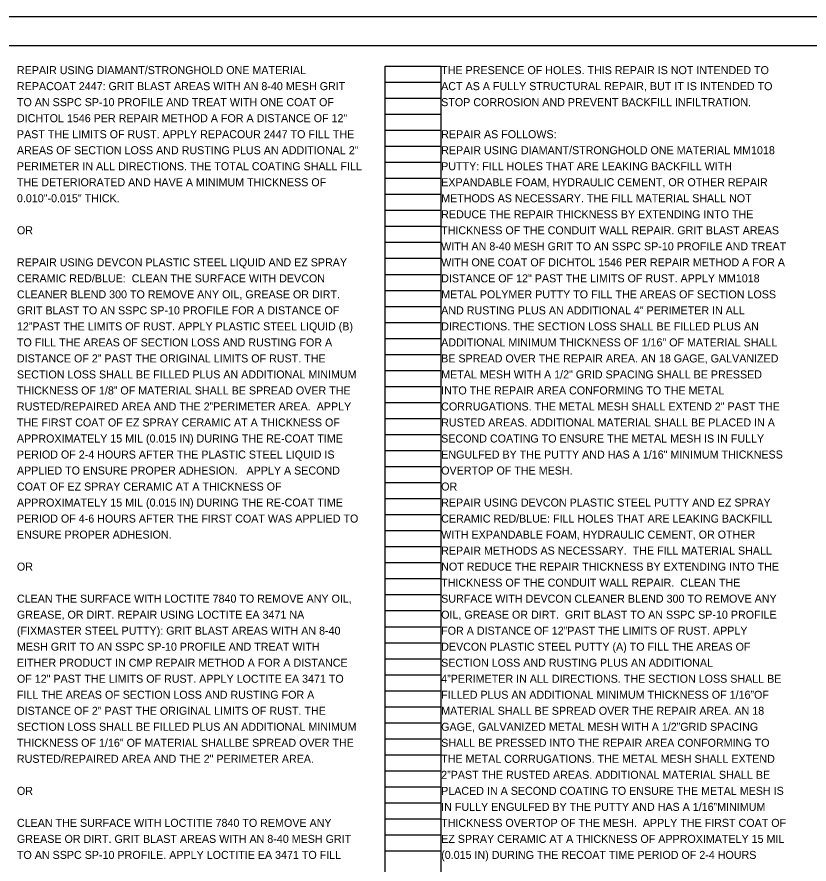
# Model space of a CAD drawing. Extents: x 0 to 42.3, y -7.4 to 22.
# Drawn here: x 9.82 to 23.67, y 7.19 to 22 of the extents above; entities that cross this region are included whole.
import ezdxf

# ---------------------------------------------------------------- set-up
doc = ezdxf.new("R2010")
doc.units = 0
for name, color, linetype in [('SH_Border', 7, 'Continuous'), ('SH_Cut_Line', 7, 'Continuous'), ('SH_Data', 7, 'Continuous'), ('SH_Text', 7, 'Continuous')]:
    doc.layers.add(name, color=color, linetype=linetype)

msp = doc.modelspace()

# ---------------------------------------------------------------- linework, layer by layer
at = {"layer": 'SH_Border'}
msp.add_lwpolyline([(1.5, 21.5), (33.5, 21.5), (33.5, 0.5), (1.5, 0.5)], close=True, dxfattribs=at)
at = {"layer": 'SH_Cut_Line'}
msp.add_lwpolyline([(0, 0), (34, 0), (34, 22), (0, 22)], close=True, dxfattribs=at)
at = {"layer": 'SH_Data'}
for p, q in [((16.26, 0.98), (16.26, 21.14)), ((16.26, 21.14), (17.24, 21.14)), ((17.24, 0.98), (17.24, 21.14)), ((16.26, 20.86), (17.24, 20.86)), ((16.26, 20.58), (17.24, 20.58)), ((16.26, 20.3), (17.24, 20.3)), ((16.26, 20.02), (17.24, 20.02)), ((16.26, 19.74), (17.24, 19.74)), ((16.26, 19.46), (17.24, 19.46)), ((16.26, 19.18), (17.24, 19.18)), ((16.26, 18.9), (17.24, 18.9)), ((16.26, 18.62), (17.24, 18.62)), ((16.26, 18.34), (17.24, 18.34)), ((16.26, 18.06), (17.24, 18.06)), ((16.26, 17.78), (17.24, 17.78)), ((16.26, 17.5), (17.24, 17.5)), ((16.26, 17.22), (17.24, 17.22)), ((16.26, 16.94), (17.24, 16.94)), ((16.26, 16.66), (17.24, 16.66)), ((16.26, 16.38), (17.24, 16.38)), ((16.26, 16.1), (17.24, 16.1)), ((16.26, 15.82), (17.24, 15.82)), ((16.26, 15.54), (17.24, 15.54)), ((16.26, 15.26), (17.24, 15.26)), ((16.26, 14.98), (17.24, 14.98)), ((16.26, 14.7), (17.24, 14.7)), ((16.26, 14.42), (17.24, 14.42)), ((16.26, 14.14), (17.24, 14.14)), ((16.26, 13.86), (17.24, 13.86)), ((16.26, 13.58), (17.24, 13.58)), ((16.26, 13.3), (17.24, 13.3)), ((16.26, 13.02), (17.24, 13.02)), ((16.26, 12.74), (17.24, 12.74)), ((16.26, 12.46), (17.24, 12.46)), ((16.26, 12.18), (17.24, 12.18)), ((16.26, 11.9), (17.24, 11.9)), ((16.26, 11.62), (17.24, 11.62)), ((16.26, 11.34), (17.24, 11.34)), ((16.26, 11.06), (17.24, 11.06)), ((16.26, 10.78), (17.24, 10.78)), ((16.26, 10.5), (17.24, 10.5)), ((16.26, 10.22), (17.24, 10.22)), ((16.26, 9.94), (17.24, 9.94)), ((16.26, 9.66), (17.24, 9.66)), ((16.26, 9.38), (17.24, 9.38)), ((16.26, 9.1), (17.24, 9.1)), ((16.26, 8.82), (17.24, 8.82)), ((16.26, 8.54), (17.24, 8.54)), ((16.26, 8.26), (17.24, 8.26)), ((16.26, 7.98), (17.24, 7.98)), ((16.26, 7.7), (17.24, 7.7)), ((16.26, 7.42), (17.24, 7.42))]:
    msp.add_line(p, q, dxfattribs=at)

# ---------------------------------------------------------------- texts
at = {"layer": 'SH_Text'}
for s, p in [('REPAIR USING DIAMANT/STRONGHOLD ONE MATERIAL ', (9.82, 21)), ('THE PRESENCE OF HOLES. THIS REPAIR IS NOT INTENDED TO ', (17.24, 21)), ('REPACOAT 2447: GRIT BLAST AREAS WITH AN 8-40 MESH GRIT ', (9.82, 20.72)), ('ACT AS A FULLY STRUCTURAL REPAIR, BUT IT IS INTENDED TO ', (17.24, 20.72)), ('TO AN SSPC SP-10 PROFILE AND TREAT WITH ONE COAT OF ', (9.82, 20.44)), ('STOP CORROSION AND PREVENT BACKFILL INFILTRATION.', (17.24, 20.44)), ('DICHTOL 1546 PER REPAIR METHOD A FOR A DISTANCE OF 12" ', (9.82, 20.16)), ('PAST THE LIMITS OF RUST. APPLY REPACOUR 2447 TO FILL THE ', (9.82, 19.88)), ('REPAIR AS FOLLOWS:', (17.24, 19.88)), ('AREAS OF SECTION LOSS AND RUSTING PLUS AN ADDITIONAL 2" ', (9.82, 19.6)), ('REPAIR USING DIAMANT/STRONGHOLD ONE MATERIAL MM1018 ', (17.24, 19.6)), ('PERIMETER IN ALL DIRECTIONS. THE TOTAL COATING SHALL FILL ', (9.82, 19.32)), ('PUTTY: FILL HOLES THAT ARE LEAKING BACKFILL WITH ', (17.24, 19.32)), ('THE DETERIORATED AND HAVE A MINIMUM THICKNESS OF ', (9.82, 19.04)), ('EXPANDABLE FOAM, HYDRAULIC CEMENT, OR OTHER REPAIR ', (17.24, 19.04)), ('0.010"-0.015" THICK.', (9.82, 18.76)), ('METHODS AS NECESSARY. THE FILL MATERIAL SHALL NOT ', (17.24, 18.76)), ('REDUCE THE REPAIR THICKNESS BY EXTENDING INTO THE ', (17.24, 18.48)), ('OR', (9.82, 18.2)), ('THICKNESS OF THE CONDUIT WALL REPAIR. GRIT BLAST AREAS ', (17.24, 18.2)), ('WITH AN 8-40 MESH GRIT TO AN SSPC SP-10 PROFILE AND TREAT ', (17.24, 17.92)), ('REPAIR USING DEVCON PLASTIC STEEL LIQUID AND EZ SPRAY ', (9.82, 17.64)), ('WITH ONE COAT OF DICHTOL 1546 PER REPAIR METHOD A FOR A ', (17.24, 17.64)), ('CERAMIC RED/BLUE: \xa0CLEAN THE SURFACE WITH DEVCON ', (9.82, 17.36)), ('DISTANCE OF 12" PAST THE LIMITS OF RUST. APPLY MM1018 ', (17.24, 17.36)), ('CLEANER BLEND 300 TO REMOVE ANY OIL, GREASE OR DIRT.\xa0', (9.82, 17.08)), ('METAL POLYMER PUTTY TO FILL THE AREAS OF SECTION LOSS ', (17.24, 17.08)), ('GRIT BLAST TO AN SSPC SP-10 PROFILE FOR A DISTANCE OF ', (9.82, 16.8)), ('AND RUSTING PLUS AN ADDITIONAL 4" PERIMETER IN ALL ', (17.24, 16.8)), ('12”PAST THE LIMITS OF RUST. APPLY\xa0PLASTIC STEEL LIQUID (B)\xa0', (9.82, 16.52)), ('DIRECTIONS. THE SECTION LOSS SHALL BE FILLED PLUS AN ', (17.24, 16.52)), ('TO FILL THE AREAS OF SECTION LOSS AND RUSTING FOR A ', (9.82, 16.24)), ('ADDITIONAL MINIMUM THICKNESS OF 1/16" OF MATERIAL SHALL ', (17.24, 16.24)), ('DISTANCE OF 2” PAST THE ORIGINAL LIMITS OF RUST. THE ', (9.82, 15.96)), ('BE SPREAD OVER THE REPAIR AREA. AN 18 GAGE, GALVANIZED ', (17.24, 15.96)), ('SECTION LOSS SHALL BE FILLED PLUS AN ADDITIONAL MINIMUM ', (9.82, 15.68)), ('METAL MESH WITH A 1/2" GRID SPACING SHALL BE PRESSED ', (17.24, 15.68)), ('THICKNESS OF\xa01/8”\xa0OF MATERIAL SHALL BE SPREAD OVER THE ', (9.82, 15.4)), ('INTO THE REPAIR AREA CONFORMING TO THE METAL ', (17.24, 15.4)), ('RUSTED/REPAIRED AREA AND THE 2”PERIMETER AREA. \xa0APPLY ', (9.82, 15.12)), ('CORRUGATIONS. THE METAL MESH SHALL EXTEND 2" PAST THE ', (17.24, 15.12)), ('THE FIRST COAT OF\xa0EZ SPRAY CERAMIC AT A THICKNESS OF ', (9.82, 14.84)), ('RUSTED AREAS. ADDITIONAL MATERIAL SHALL BE PLACED IN A ', (17.24, 14.84)), ('APPROXIMATELY 15 MIL (0.015 IN) DURING THE RE-COAT TIME ', (9.82, 14.56)), ('SECOND COATING TO ENSURE THE METAL MESH IS IN FULLY ', (17.24, 14.56)), ('PERIOD\xa0OF 2-4 HOURS\xa0AFTER\xa0THE PLASTIC STEEL LIQUID IS ', (9.82, 14.28)), ('ENGULFED BY THE PUTTY AND HAS A 1/16" MINIMUM THICKNESS ', (17.24, 14.28)), ('APPLIED TO ENSURE PROPER ADHESION.\xa0 \xa0APPLY A SECOND ', (9.82, 14)), ('OVERTOP OF THE MESH. ', (17.24, 14)), ('COAT OF EZ SPRAY CERAMIC AT A THICKNESS OF ', (9.82, 13.72)), ('OR', (17.24, 13.72)), ('APPROXIMATELY 15 MIL (0.015 IN) DURING THE\xa0RE-COAT\xa0TIME ', (9.82, 13.44)), ('REPAIR USING DEVCON PLASTIC STEEL PUTTY AND EZ SPRAY ', (17.24, 13.44)), ('PERIOD OF 4-6 HOURS AFTER THE FIRST COAT WAS APPLIED TO ', (9.82, 13.16)), ('CERAMIC RED/BLUE:\xa0FILL HOLES THAT ARE LEAKING BACKFILL ', (17.24, 13.16)), ('ENSURE PROPER ADHESION.', (9.82, 12.88)), ('WITH EXPANDABLE FOAM, HYDRAULIC CEMENT, OR OTHER ', (17.24, 12.88)), ('REPAIR METHODS AS NECESSARY. \xa0THE FILL MATERIAL SHALL ', (17.24, 12.6)), ('OR', (9.82, 12.32)), ('NOT REDUCE THE REPAIR THICKNESS BY EXTENDING INTO THE ', (17.24, 12.32)), ('THICKNESS OF THE CONDUIT WALL REPAIR. \xa0CLEAN THE ', (17.24, 12.04)), ('CLEAN THE SURFACE WITH LOCTITE 7840 TO REMOVE ANY OIL, ', (9.82, 11.76)), ('SURFACE WITH DEVCON CLEANER BLEND 300 TO REMOVE ANY ', (17.24, 11.76)), ('GREASE, OR DIRT. REPAIR USING LOCTITE EA 3471 NA ', (9.82, 11.48)), ('OIL, GREASE OR DIRT. \xa0GRIT BLAST TO AN SSPC SP-10 PROFILE\xa0', (17.24, 11.48)), ('(FIXMASTER STEEL PUTTY): GRIT BLAST AREAS WITH AN 8-40 ', (9.82, 11.2)), ('FOR A DISTANCE OF 12”PAST THE LIMITS OF RUST. APPLY ', (17.24, 11.2)), ('MESH GRIT TO AN SSPC SP-10 PROFILE AND TREAT WITH ', (9.82, 10.92)), ('DEVCON PLASTIC STEEL PUTTY (A) TO FILL THE AREAS OF ', (17.24, 10.92)), ('EITHER PRODUCT IN CMP REPAIR METHOD A FOR A DISTANCE ', (9.82, 10.64)), ('SECTION LOSS AND RUSTING PLUS AN ADDITIONAL ', (17.24, 10.64)), ('OF 12" PAST THE LIMITS OF RUST. APPLY LOCTITE EA 3471 TO ', (9.82, 10.36)), ('4”PERIMETER IN ALL DIRECTIONS. THE SECTION LOSS SHALL BE ', (17.24, 10.36)), ('FILL THE AREAS OF SECTION LOSS AND RUSTING FOR A ', (9.82, 10.08)), ('FILLED PLUS AN ADDITIONAL MINIMUM THICKNESS OF 1/16”OF ', (17.24, 10.08)), ('DISTANCE OF 2" PAST THE ORIGINAL LIMITS OF RUST. THE ', (9.82, 9.8)), ('MATERIAL SHALL BE SPREAD OVER THE REPAIR AREA. AN 18 ', (17.24, 9.8)), ('SECTION LOSS SHALL BE FILLED PLUS AN ADDITIONAL MINIMUM ', (9.82, 9.52)), ('GAGE, GALVANIZED METAL MESH WITH A 1/2”GRID SPACING', (17.24, 9.52)), ('THICKNESS OF 1/16" OF MATERIAL SHALLBE SPREAD OVER THE ', (9.82, 9.24)), ('SHALL BE PRESSED INTO THE REPAIR AREA CONFORMING TO ', (17.24, 9.24)), ('RUSTED/REPAIRED AREA AND THE 2" PERIMETER AREA.', (9.82, 8.96)), ('THE METAL CORRUGATIONS. THE METAL MESH SHALL EXTEND ', (17.24, 8.96)), ('2”PAST THE RUSTED AREAS. ADDITIONAL MATERIAL SHALL BE ', (17.24, 8.68)), ('OR', (9.82, 8.4)), ('PLACED IN A SECOND COATING TO ENSURE THE METAL MESH IS ', (17.24, 8.4)), ('IN FULLY ENGULFED BY THE PUTTY AND HAS A 1/16”MINIMUM ', (17.24, 8.12)), ('CLEAN THE SURFACE WITH LOCTITIE 7840 TO REMOVE ANY ', (9.82, 7.84)), ('THICKNESS OVERTOP OF THE MESH. \xa0APPLY THE FIRST COAT OF\xa0', (17.24, 7.84)), ('GREASE OR DIRT. GRIT BLAST AREAS WITH AN 8-40 MESH GRIT ', (9.82, 7.56)), ('EZ SPRAY CERAMIC AT A THICKNESS OF APPROXIMATELY 15 MIL ', (17.24, 7.56)), ('TO AN SSPC SP-10 PROFILE. APPLY LOCTITIE EA 3471 TO FILL ', (9.82, 7.28)), ('(0.015 IN) DURING THE RECOAT TIME PERIOD\xa0OF 2-4 HOURS\xa0', (17.24, 7.28))]:
    msp.add_text(s, height=0.14, dxfattribs=at).set_placement(p)

doc.saveas('drawing.dxf')
